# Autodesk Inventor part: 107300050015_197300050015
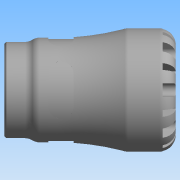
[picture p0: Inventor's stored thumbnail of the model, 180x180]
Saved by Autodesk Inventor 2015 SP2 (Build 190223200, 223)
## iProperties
Created: 2016-12
Part Number: 107300050015_197300050015
Material: Generic
Description: PLASSON FEMALE INTEGRAL BRASS THREAD 50X1.1/2" SERIES 1
Document SubType Name: Modeling
Designer: KIM
Density: 1 g/cm^3
Appearance: Default
Author: KIM
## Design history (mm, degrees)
derived "1073.ipt"
feature "Solid1::1073.ipt"
tag "TaggingFeature1"
body "Solid1"
other parameters: "d0" = 118, "d1" = 34.02, "d3" = 62.5, "d4" = 85, "d6" = 81, "d8" = 72.25, "d13" = 9, "d14" = 9, "d15" = 0, "d17" = 360 deg, "d19" = 8 deg, "d20" = 1, "d21" = 1, "d22" = 8 deg, "d24" = 0, "d26" = 360 deg, "d32" = 8.5, "d33" = 8.5, "d39" = 1.34535, "d42" = 44.845, "d43" = 66.3, "d46" = 4.16667, "d47" = 21, "d48" = 42.60275, "d50" = 5.28, "d51" = 0.85, "d54" = 17.5, "d55" = 11, "d57" = 17.64, "d58" = 0, "d68" = 360 deg, "d72" = 1, "d74" = 0, "d76" = 14.875, "E_" = 85, "H_" = 118, "l_" = 81, "G_" = 44.845, "l_2" = 21, "d9" = 11.25, "d11" = 85, "d12" = 62.5, "d49" = 16
